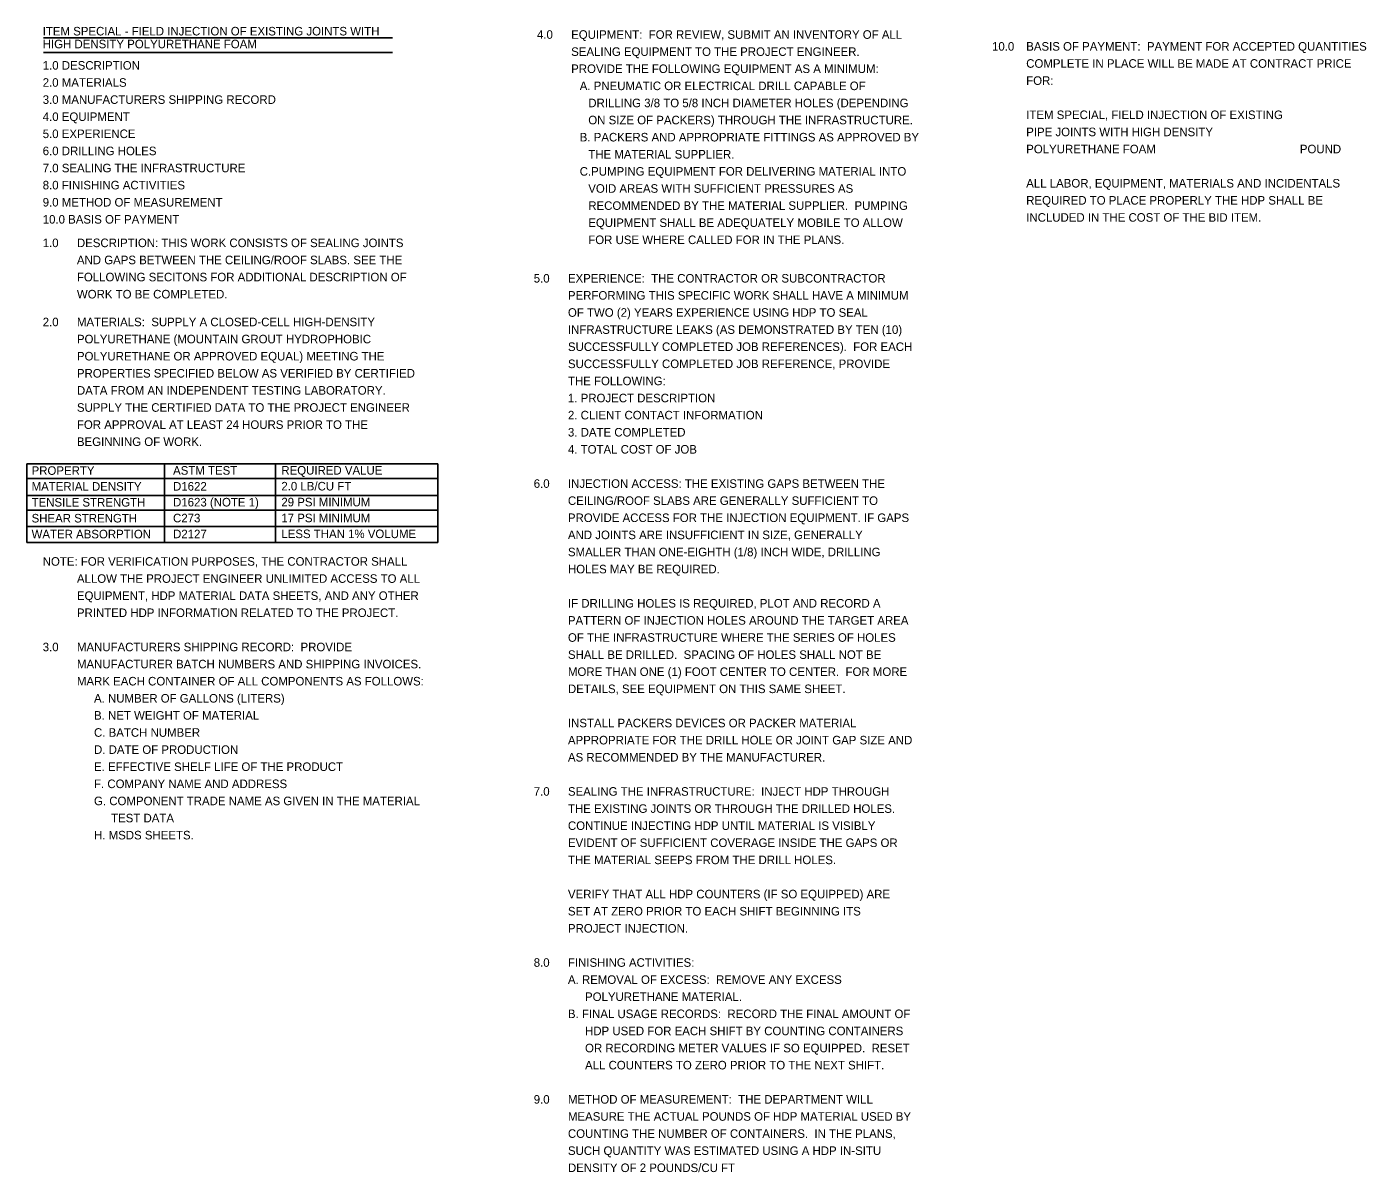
# Model space of a CAD drawing. Extents: x 0 to 63.6, y 0 to 22.
# Drawn here: x 41.68 to 63.61, y 1.54 to 20.29 of the extents above; entities that cross this region are included whole.
import ezdxf

# ---------------------------------------------------------------- set-up
doc = ezdxf.new("R2010")
doc.units = 0
doc.layers.add('SC_Scratch1', color=7, linetype='Continuous')

msp = doc.modelspace()

# ---------------------------------------------------------------- linework, layer by layer
at = {"layer": 'SC_Scratch1'}
for p, q in [((41.951, 20.112), (47.664, 20.112)), ((41.951, 19.872), (47.664, 19.872)), ((41.678, 13.138), (48.408, 13.138)), ((41.678, 13.138), (41.678, 11.851)), ((43.931, 13.138), (43.931, 11.851)), ((45.749, 13.138), (45.749, 11.851)), ((48.408, 13.138), (48.408, 11.851)), ((41.678, 12.896), (48.408, 12.896)), ((46.071, 12.896), (47.366, 12.896)), ((46.071, 12.896), (47.366, 12.896)), ((41.678, 12.62), (48.408, 12.62)), ((41.678, 12.378), (48.408, 12.378)), ((41.678, 12.114), (48.408, 12.114)), ((41.678, 11.851), (48.408, 11.851))]:
    msp.add_line(p, q, dxfattribs=at)

# ---------------------------------------------------------------- texts
for s, p in [('ITEM SPECIAL - FIELD INJECTION OF EXISTING JOINTS WITH ', (41.939, 20.15)), ('4.0', (50.031, 20.095)), ('EQUIPMENT:  FOR REVIEW, SUBMIT AN INVENTORY OF ALL ', (50.591, 20.095)), ('HIGH DENSITY POLYURETHANE FOAM', (41.939, 19.94)), ('SEALING EQUIPMENT TO THE PROJECT ENGINEER.  ', (50.591, 19.815)), ('10.0', (57.481, 19.901)), ('BASIS OF PAYMENT:  PAYMENT FOR ACCEPTED QUANTITIES ', (58.041, 19.901)), ('COMPLETE IN PLACE WILL BE MADE AT CONTRACT PRICE ', (58.041, 19.621)), ('1.0 DESCRIPTION', (41.939, 19.59)), ('PROVIDE THE FOLLOWING EQUIPMENT AS A MINIMUM:', (50.591, 19.535)), ('2.0 MATERIALS', (41.939, 19.31)), ('A. PNEUMATIC OR ELECTRICAL DRILL CAPABLE OF ', (50.731, 19.255)), ('FOR:', (58.041, 19.341)), ('3.0 MANUFACTURERS SHIPPING RECORD', (41.939, 19.03)), ('DRILLING 3/8 TO 5/8 INCH DIAMETER HOLES (DEPENDING ', (50.871, 18.975)), ('4.0 EQUIPMENT', (41.939, 18.75)), ('ITEM SPECIAL, FIELD INJECTION OF EXISTING ', (58.041, 18.781)), ('ON SIZE OF PACKERS) THROUGH THE INFRASTRUCTURE.', (50.871, 18.695)), ('PIPE JOINTS WITH HIGH DENSITY ', (58.041, 18.501)), ('5.0 EXPERIENCE', (41.939, 18.47)), ('B. PACKERS AND APPROPRIATE FITTINGS AS APPROVED BY ', (50.731, 18.415)), ('6.0 DRILLING HOLES', (41.939, 18.19)), ('THE MATERIAL SUPPLIER.', (50.871, 18.135)), ('POLYURETHANE FOAM', (58.041, 18.221)), ('POUND', (62.521, 18.221)), ('7.0 SEALING THE INFRASTRUCTURE', (41.939, 17.91)), ('C.PUMPING EQUIPMENT FOR DELIVERING MATERIAL INTO ', (50.731, 17.855)), ('8.0 FINISHING ACTIVITIES', (41.939, 17.63)), ('ALL LABOR, EQUIPMENT, MATERIALS AND INCIDENTALS ', (58.041, 17.661)), ('VOID AREAS WITH SUFFICIENT PRESSURES AS ', (50.871, 17.575)), ('9.0 METHOD OF MEASUREMENT', (41.939, 17.35)), ('RECOMMENDED BY THE MATERIAL SUPPLIER.  PUMPING ', (50.871, 17.295)), ('REQUIRED TO PLACE PROPERLY THE HDP SHALL BE ', (58.041, 17.381)), ('10.0 BASIS OF PAYMENT', (41.939, 17.07)), ('EQUIPMENT SHALL BE ADEQUATELY MOBILE TO ALLOW ', (50.871, 17.015)), ('INCLUDED IN THE COST OF THE BID ITEM.', (58.041, 17.101)), ('1.0 ', (41.939, 16.685)), ('DESCRIPTION: THIS WORK CONSISTS OF SEALING JOINTS ', (42.499, 16.685)), ('FOR USE WHERE CALLED FOR IN THE PLANS.', (50.871, 16.735)), ('AND GAPS BETWEEN THE CEILING/ROOF SLABS. SEE THE ', (42.499, 16.405)), ('FOLLOWING SECITONS FOR ADDITIONAL DESCRIPTION OF ', (42.499, 16.125)), ('5.0', (49.978, 16.105)), ('EXPERIENCE:  THE CONTRACTOR OR SUBCONTRACTOR ', (50.538, 16.105)), ('WORK TO BE COMPLETED.', (42.499, 15.845)), ('PERFORMING THIS SPECIFIC WORK SHALL HAVE A MINIMUM ', (50.538, 15.825)), ('OF TWO (2) YEARS EXPERIENCE USING HDP TO SEAL ', (50.538, 15.545)), ('2.0', (41.939, 15.39)), ('MATERIALS:  SUPPLY A CLOSED-CELL HIGH-DENSITY ', (42.499, 15.39)), ('INFRASTRUCTURE LEAKS (AS DEMONSTRATED BY TEN (10) ', (50.538, 15.265)), ('POLYURETHANE (MOUNTAIN GROUT HYDROPHOBIC ', (42.499, 15.11)), ('SUCCESSFULLY COMPLETED JOB REFERENCES).  FOR EACH ', (50.538, 14.985)), ('POLYURETHANE OR APPROVED EQUAL) MEETING THE ', (42.499, 14.83)), ('SUCCESSFULLY COMPLETED JOB REFERENCE, PROVIDE ', (50.538, 14.705)), ('PROPERTIES SPECIFIED BELOW AS VERIFIED BY CERTIFIED ', (42.499, 14.55)), ('THE FOLLOWING:', (50.538, 14.425)), ('DATA FROM AN INDEPENDENT TESTING LABORATORY.  ', (42.499, 14.27)), ('1. PROJECT DESCRIPTION', (50.538, 14.145)), ('SUPPLY THE CERTIFIED DATA TO THE PROJECT ENGINEER ', (42.499, 13.99)), ('FOR APPROVAL AT LEAST 24 HOURS PRIOR TO THE ', (42.499, 13.71)), ('2. CLIENT CONTACT INFORMATION', (50.538, 13.865)), ('3. DATE COMPLETED', (50.538, 13.585)), ('BEGINNING OF WORK.', (42.499, 13.43)), ('4. TOTAL COST OF JOB', (50.538, 13.305)), ('6.0', (49.978, 12.745)), ('INJECTION ACCESS: THE EXISTING GAPS BETWEEN THE ', (50.538, 12.745)), ('CEILING/ROOF SLABS ARE GENERALLY SUFFICIENT TO ', (50.538, 12.465)), ('PROVIDE ACCESS FOR THE INJECTION EQUIPMENT. IF GAPS ', (50.538, 12.185)), ('AND JOINTS ARE INSUFFICIENT IN SIZE, GENERALLY ', (50.538, 11.905)), ('SMALLER THAN ONE-EIGHTH (1/8) INCH WIDE, DRILLING ', (50.538, 11.625)), ('NOTE: FOR VERIFICATION PURPOSES, THE CONTRACTOR SHALL ', (41.939, 11.47)), ('HOLES MAY BE REQUIRED. ', (50.538, 11.345)), ('ALLOW THE PROJECT ENGINEER UNLIMITED ACCESS TO ALL ', (42.499, 11.19)), ('EQUIPMENT, HDP MATERIAL DATA SHEETS, AND ANY OTHER ', (42.499, 10.91)), ('PRINTED HDP INFORMATION RELATED TO THE PROJECT.', (42.499, 10.63)), ('IF DRILLING HOLES IS REQUIRED, PLOT AND RECORD A ', (50.538, 10.785)), ('PATTERN OF INJECTION HOLES AROUND THE TARGET AREA ', (50.538, 10.505)), ('OF THE INFRASTRUCTURE WHERE THE SERIES OF HOLES ', (50.538, 10.225)), ('3.0', (41.939, 10.07)), ('MANUFACTURERS SHIPPING RECORD:  PROVIDE ', (42.499, 10.07)), ('MANUFACTURER BATCH NUMBERS AND SHIPPING INVOICES.  ', (42.499, 9.79)), ('SHALL BE DRILLED.  SPACING OF HOLES SHALL NOT BE ', (50.538, 9.945)), ('MARK EACH CONTAINER OF ALL COMPONENTS AS FOLLOWS:', (42.499, 9.51)), ('MORE THAN ONE (1) FOOT CENTER TO CENTER.  FOR MORE ', (50.538, 9.665)), ('DETAILS, SEE EQUIPMENT ON THIS SAME SHEET.', (50.538, 9.385)), ('A. NUMBER OF GALLONS (LITERS)', (42.779, 9.23)), ('B. NET WEIGHT OF MATERIAL', (42.779, 8.95)), ('C. BATCH NUMBER', (42.779, 8.67)), ('INSTALL PACKERS DEVICES OR PACKER MATERIAL ', (50.538, 8.825)), ('APPROPRIATE FOR THE DRILL HOLE OR JOINT GAP SIZE AND ', (50.538, 8.545)), ('D. DATE OF PRODUCTION', (42.779, 8.39)), ('AS RECOMMENDED BY THE MANUFACTURER.', (50.538, 8.265)), ('E. EFFECTIVE SHELF LIFE OF THE PRODUCT', (42.779, 8.11)), ('F. COMPANY NAME AND ADDRESS', (42.779, 7.83)), ('G. COMPONENT TRADE NAME AS GIVEN IN THE MATERIAL ', (42.779, 7.55)), ('7.0', (49.978, 7.705)), ('SEALING THE INFRASTRUCTURE:  INJECT HDP THROUGH ', (50.538, 7.705)), ('THE EXISTING JOINTS OR THROUGH THE DRILLED HOLES.  ', (50.538, 7.425)), ('TEST DATA', (43.059, 7.27)), ('CONTINUE INJECTING HDP UNTIL MATERIAL IS VISIBLY ', (50.538, 7.145)), ('H. MSDS SHEETS.', (42.779, 6.99)), ('EVIDENT OF SUFFICIENT COVERAGE INSIDE THE GAPS OR ', (50.538, 6.865)), ('THE MATERIAL SEEPS FROM THE DRILL HOLES.', (50.538, 6.585)), ('VERIFY THAT ALL HDP COUNTERS (IF SO EQUIPPED) ARE ', (50.538, 6.025)), ('SET AT ZERO PRIOR TO EACH SHIFT BEGINNING ITS ', (50.538, 5.745)), ('PROJECT INJECTION.', (50.538, 5.465)), ('8.0', (49.978, 4.905)), ('FINISHING ACTIVITIES:', (50.538, 4.905)), ('A. REMOVAL OF EXCESS:  REMOVE ANY EXCESS ', (50.538, 4.625)), ('POLYURETHANE MATERIAL.', (50.818, 4.345)), ('B. FINAL USAGE RECORDS:  RECORD THE FINAL AMOUNT OF ', (50.538, 4.065)), ('HDP USED FOR EACH SHIFT BY COUNTING CONTAINERS ', (50.818, 3.785)), ('OR RECORDING METER VALUES IF SO EQUIPPED.  RESET ', (50.818, 3.505)), ('ALL COUNTERS TO ZERO PRIOR TO THE NEXT SHIFT.', (50.818, 3.225)), ('9.0', (49.978, 2.665)), ('METHOD OF MEASUREMENT:  THE DEPARTMENT WILL ', (50.538, 2.665)), ('MEASURE THE ACTUAL POUNDS OF HDP MATERIAL USED BY ', (50.538, 2.385)), ('COUNTING THE NUMBER OF CONTAINERS.  IN THE PLANS, ', (50.538, 2.105)), ('SUCH QUANTITY WAS ESTIMATED USING A HDP IN-SITU ', (50.538, 1.825)), ('DENSITY OF 2 POUNDS/CU FT', (50.538, 1.545))]:
    msp.add_text(s, height=0.14, rotation=360, dxfattribs=at).set_placement(p)
for s, p in [('PROPERTY', (41.757, 12.958)), ('ASTM TEST', (44.073, 12.96)), ('REQUIRED VALUE', (45.846, 12.962)), ('MATERIAL DENSITY', (41.757, 12.698)), ('D1622', (44.073, 12.7)), ('2.0 LB/CU FT', (45.846, 12.702)), ('TENSILE STRENGTH', (41.757, 12.438)), ('D1623 (NOTE 1)', (44.073, 12.44)), ('29 PSI MINIMUM', (45.846, 12.442)), ('SHEAR STRENGTH', (41.757, 12.178)), ('C273', (44.073, 12.18)), ('17 PSI MINIMUM', (45.846, 12.182)), ('D2127', (44.073, 11.92)), ('LESS THAN 1% VOLUME', (45.846, 11.922)), ('WATER ABSORPTION', (41.757, 11.918))]:
    msp.add_text(s, height=0.14, dxfattribs=at).set_placement(p)

doc.saveas('drawing.dxf')
